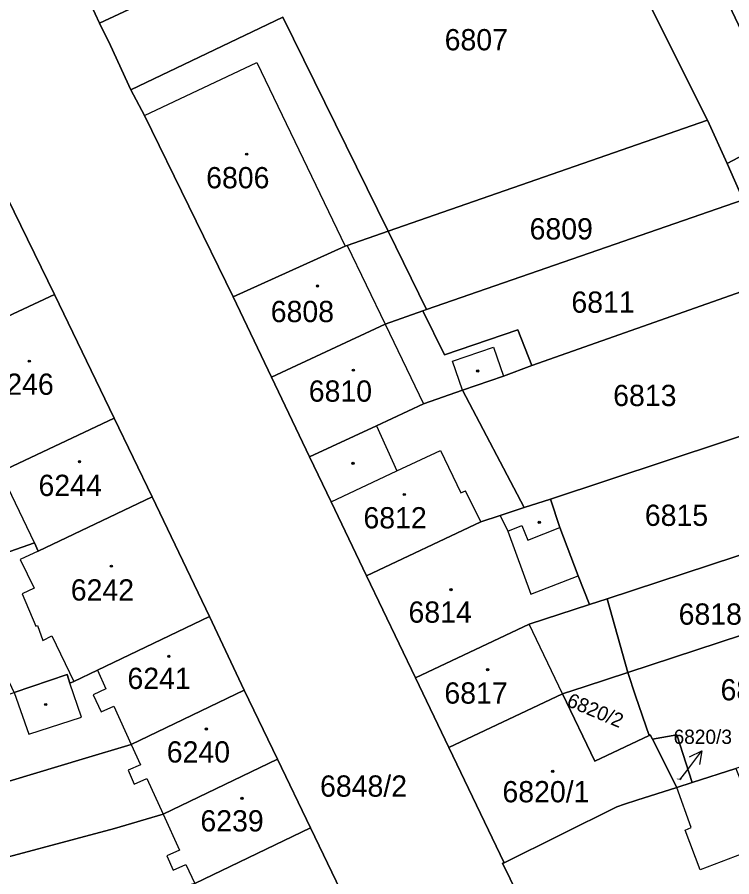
# Model space of a CAD drawing. Extents: x -596233 to -595156, y -1161235 to -1159375.
# Drawn here: x -595504.1 to -595447, y -1160101.5 to -1160032.8 of the extents above; entities that cross this region are included whole.
import ezdxf

# ---------------------------------------------------------------- set-up
doc = ezdxf.new("R2010")
doc.units = 0
for name, color, linetype in [('KN_CAR_KR', 7, 'Continuous'), ('KN_KULTURY', 7, 'Continuous'), ('KN_PARC_CIS_POM', 7, 'Continuous'), ('KN_PARC_CIS_POZ', 7, 'Continuous'), ('KN_PARC_CIS_STAV', 7, 'Continuous'), ('KN_PARC_PLOCHA', 7, 'Continuous'), ('PARC_C_SIPKA', 7, 'Continuous'), ('parcely_l', 7, 'Continuous')]:
    doc.layers.add(name, color=color, linetype=linetype)

msp = doc.modelspace()

# ---------------------------------------------------------------- linework, layer by layer
at = {"layer": 'KN_CAR_KR'}
for points in [[(-595493.94, -1160040.65), (-595484.95, -1160036.42)], [(-595484.95, -1160036.42), (-595477.89, -1160051.1)], [(-595477.75, -1160051.04), (-595474.71, -1160057.33)], [(-595474.71, -1160057.33), (-595471.63, -1160063.71)], [(-595469.32, -1160060.3), (-595466.04, -1160059.17)], [(-595466.04, -1160059.17), (-595465.25, -1160061.51)], [(-595468.52, -1160062.61), (-595469.32, -1160060.3)], [(-595475.39, -1160065.46), (-595473.77, -1160069.08)], [(-595473.77, -1160069.08), (-595470.29, -1160067.44)], [(-595470.29, -1160067.44), (-595468.66, -1160070.83)], [(-595502.74, -1160074.83), (-595505.44, -1160069.16)], [(-595479.01, -1160071.55), (-595473.77, -1160069.08)], [(-595468.66, -1160070.83), (-595468.29, -1160070.68)], [(-595467.06, -1160073.15), (-595468.29, -1160070.68)], [(-595465.51, -1160072.64), (-595464.89, -1160073.89)], [(-595464.89, -1160073.89), (-595463.77, -1160073.44)], [(-595463.77, -1160073.44), (-595463.31, -1160074.61)], [(-595463.31, -1160074.61), (-595460.74, -1160073.59)], [(-595464.89, -1160073.89), (-595463.07, -1160078.93)], [(-595502.43, -1160075.48), (-595503.87, -1160076.17)], [(-595503.87, -1160076.17), (-595502.76, -1160078.45)], [(-595463.07, -1160078.93), (-595459.28, -1160077.47)], [(-595502.76, -1160078.45), (-595503.7, -1160078.91)], [(-595503.7, -1160078.91), (-595502.61, -1160081.48)], [(-595502.61, -1160081.48), (-595502.48, -1160081.42)], [(-595502.48, -1160081.42), (-595502.06, -1160082.62)], [(-595460.52, -1160086.9), (-595463.2, -1160081.34)], [(-595502.06, -1160082.62), (-595501.34, -1160082.27)], [(-595501.34, -1160082.27), (-595499.58, -1160085.9)], [(-595497.7, -1160085), (-595497.02, -1160086.5)], [(-595498.98, -1160088.76), (-595499.89, -1160086.05)], [(-595504.35, -1160086.79), (-595503.18, -1160090.13)], [(-595497.02, -1160086.5), (-595498.03, -1160086.97)], [(-595498.03, -1160086.97), (-595497.41, -1160088.33)], [(-595497.41, -1160088.33), (-595496.39, -1160087.87)], [(-595496.39, -1160087.87), (-595494.99, -1160090.94)], [(-595503.18, -1160090.13), (-595498.98, -1160088.76)], [(-595494.99, -1160090.94), (-595494.25, -1160092.56)], [(-595494.25, -1160092.56), (-595495.25, -1160092.99)], [(-595495.25, -1160092.99), (-595494.75, -1160094.13)], [(-595494.75, -1160094.13), (-595493.75, -1160093.67)], [(-595493.75, -1160093.67), (-595492.44, -1160096.53)], [(-595444.9, -1160099.62), (-595445.04, -1160099.25), (-595449.53, -1160100.96), (-595450.73, -1160097.79), (-595450.24, -1160097.58), (-595451.4, -1160094.38)], [(-595492.44, -1160096.53), (-595491.13, -1160099.4)], [(-595491.13, -1160099.4), (-595492.15, -1160099.86)], [(-595492.15, -1160099.86), (-595491.64, -1160101)], [(-595491.64, -1160101), (-595490.62, -1160100.53)], [(-595490.62, -1160100.53), (-595489.92, -1160102.05)]]:
    msp.add_lwpolyline(points, dxfattribs=at)
at = {"layer": 'KN_KULTURY'}
for centre, radius in [((-595485.77, -1160043.75), 0.09), ((-595485.77, -1160043.75), 0.0398), ((-595480.11, -1160054.29), 0.09), ((-595480.11, -1160054.29), 0.0398), ((-595503.15, -1160060.3), 0.09), ((-595503.15, -1160060.3), 0.0398), ((-595477.24, -1160061.02), 0.09), ((-595477.24, -1160061.02), 0.0398), ((-595467.3, -1160061.09), 0.09), ((-595467.3, -1160061.09), 0.0398), ((-595499.13, -1160068.34), 0.09), ((-595499.13, -1160068.34), 0.0398), ((-595477.27, -1160068.47), 0.09), ((-595477.27, -1160068.47), 0.0398), ((-595473.17, -1160070.96), 0.09), ((-595473.17, -1160070.96), 0.0398), ((-595462.38, -1160073.19), 0.09), ((-595462.38, -1160073.19), 0.0398), ((-595496.58, -1160076.69), 0.09), ((-595496.58, -1160076.69), 0.0398), ((-595469.44, -1160078.56), 0.09), ((-595469.44, -1160078.56), 0.0398), ((-595491.99, -1160083.9), 0.09), ((-595491.99, -1160083.9), 0.0398), ((-595466.51, -1160084.96), 0.09), ((-595466.51, -1160084.96), 0.0398), ((-595501.83, -1160087.75), 0.09), ((-595501.83, -1160087.75), 0.0398), ((-595488.99, -1160089.71), 0.09), ((-595488.99, -1160089.71), 0.0398), ((-595461.31, -1160093.1), 0.09), ((-595461.31, -1160093.1), 0.0398), ((-595486.15, -1160095.25), 0.09), ((-595486.15, -1160095.25), 0.0398)]:
    msp.add_circle(centre, radius, dxfattribs=at)
at = {"layer": 'KN_PARC_PLOCHA'}
for points in [[(-595370.66, -1159982.51), (-595383.62, -1159988.37), (-595384.8, -1159988.91), (-595396.25, -1159994.64), (-595401.63, -1159997.2), (-595446.84, -1160018.63), (-595452.27, -1160021.15), (-595442.45, -1160041.88), (-595447.38, -1160044.51), (-595448.95, -1160041.02), (-595456.31, -1160026.28), (-595465.43, -1160023.47), (-595465.73, -1160022.86), (-595449.79, -1160015.51), (-595393.91, -1159989.04), (-595388.81, -1159987.77), (-595371.9, -1159979.72)], [(-595499.33, -1159989.01), (-595508.24, -1159993.19), (-595499.43, -1160011.28), (-595492.24, -1160026.06), (-595484.15, -1160022.01), (-595482.84, -1160024), (-595481.63, -1160025.84), (-595497.53, -1160033.27), (-595499.26, -1160029.53), (-595505.27, -1160017.48), (-595516.97, -1159993.45), (-595517.07, -1159992.25), (-595516.88, -1159991.13), (-595516.34, -1159990.17), (-595515.58, -1159989.46), (-595502.19, -1159983.08)], [(-595394.56, -1159998.22), (-595390.05, -1160007.78), (-595386.48, -1160015.36), (-595392, -1160017.91), (-595391.13, -1160020.12), (-595379.95, -1160014.99), (-595375.93, -1160024.33), (-595388.83, -1160029.93), (-595390.02, -1160027.09), (-595402.97, -1160033.4), (-595406.16, -1160026.42), (-595410.19, -1160028.27), (-595404.65, -1160039.32), (-595412.81, -1160043.67), (-595414.99, -1160039.05), (-595443.86, -1160052.68), (-595446.09, -1160047.4), (-595447.38, -1160044.51), (-595442.45, -1160041.88), (-595452.27, -1160021.15), (-595446.84, -1160018.63), (-595401.63, -1159997.2), (-595396.25, -1159994.64)], [(-595465.73, -1160022.86), (-595465.43, -1160023.47), (-595456.31, -1160026.28), (-595448.95, -1160041.02), (-595474.47, -1160049.9), (-595482.88, -1160032.81), (-595495.03, -1160038.6), (-595496.65, -1160035.07), (-595497.53, -1160033.27), (-595481.63, -1160025.84), (-595474.26, -1160022.44), (-595467.59, -1160019.14)], [(-595474.47, -1160049.9), (-595477.75, -1160051.04), (-595477.89, -1160051.1), (-595486.84, -1160055.17), (-595493.94, -1160040.65), (-595495.03, -1160038.6), (-595482.88, -1160032.81)], [(-595447.38, -1160044.51), (-595446.09, -1160047.4), (-595471.41, -1160056.18), (-595474.47, -1160049.9), (-595448.95, -1160041.02)], [(-595501.14, -1160054.98), (-595510.33, -1160059.26), (-595511.18, -1160059.35), (-595514.32, -1160059.76), (-595514.63, -1160059.88), (-595517.75, -1160052.96), (-595517.37, -1160052.83), (-595513.96, -1160051.67), (-595504.89, -1160047.26)], [(-595443.86, -1160052.68), (-595443.41, -1160053.75), (-595462.98, -1160060.66), (-595464.11, -1160057.8), (-595469.97, -1160059.79), (-595471.69, -1160056.28), (-595471.41, -1160056.18), (-595446.09, -1160047.4)], [(-595471.41, -1160056.18), (-595471.69, -1160056.28), (-595474.71, -1160057.33), (-595483.78, -1160061.58), (-595486.84, -1160055.17), (-595477.89, -1160051.1), (-595477.75, -1160051.04), (-595474.47, -1160049.9)], [(-595438.76, -1160063.81), (-595442.92, -1160065.18), (-595461.5, -1160071.32), (-595463.59, -1160072.01), (-595468.52, -1160062.61), (-595465.25, -1160061.51), (-595462.98, -1160060.66), (-595443.41, -1160053.75)], [(-595496.36, -1160064.85), (-595505.44, -1160069.16), (-595506.41, -1160069.26), (-595506.71, -1160069.29), (-595509.59, -1160069.9), (-595510.25, -1160070.13), (-595512.25, -1160064.9), (-595513.19, -1160062.45), (-595514.01, -1160062.54), (-595514.81, -1160059.94), (-595514.63, -1160059.88), (-595514.32, -1160059.76), (-595511.18, -1160059.35), (-595510.33, -1160059.26), (-595501.14, -1160054.98)], [(-595462.98, -1160060.66), (-595465.25, -1160061.51), (-595468.52, -1160062.61), (-595471.63, -1160063.71), (-595475.39, -1160065.46), (-595480.74, -1160067.95), (-595483.78, -1160061.58), (-595474.71, -1160057.33), (-595471.69, -1160056.28), (-595469.97, -1160059.79), (-595464.11, -1160057.8)], [(-595463.59, -1160072.01), (-595465.51, -1160072.64), (-595467.06, -1160073.15), (-595476.19, -1160077.46), (-595479.01, -1160071.55), (-595480.74, -1160067.95), (-595475.39, -1160065.46), (-595471.63, -1160063.71), (-595468.52, -1160062.61)], [(-595493.31, -1160071.14), (-595502.43, -1160075.48), (-595502.74, -1160074.83), (-595507.22, -1160076.4), (-595509.59, -1160069.9), (-595506.71, -1160069.29), (-595506.41, -1160069.26), (-595505.44, -1160069.16), (-595496.36, -1160064.85)], [(-595440.53, -1160073.9), (-595456.96, -1160079.29), (-595458.38, -1160079.76), (-595459.28, -1160077.47), (-595460.74, -1160073.59), (-595461.5, -1160071.32), (-595442.92, -1160065.18)], [(-595488.75, -1160080.72), (-595497.7, -1160085), (-595499.58, -1160085.9), (-595499.89, -1160086.05), (-595500.12, -1160085.35), (-595504.35, -1160086.79), (-595508.97, -1160077.01), (-595507.22, -1160076.4), (-595502.74, -1160074.83), (-595502.43, -1160075.48), (-595493.31, -1160071.14)], [(-595458.38, -1160079.76), (-595463.2, -1160081.34), (-595472.29, -1160085.62), (-595476.19, -1160077.46), (-595467.06, -1160073.15), (-595465.51, -1160072.64), (-595463.59, -1160072.01), (-595461.5, -1160071.32), (-595460.74, -1160073.59), (-595459.28, -1160077.47)], [(-595440.45, -1160074.17), (-595438.83, -1160079.78), (-595455.3, -1160085.19), (-595456.96, -1160079.29), (-595440.53, -1160073.9)], [(-595455.3, -1160085.19), (-595458.71, -1160086.31), (-595460.52, -1160086.9), (-595469.62, -1160091.2), (-595472.29, -1160085.62), (-595463.2, -1160081.34), (-595458.38, -1160079.76), (-595456.96, -1160079.29)], [(-595435.31, -1160089.22), (-595446.67, -1160092.86), (-595450.17, -1160093.99), (-595451.39, -1160090.18), (-595453.34, -1160090.52), (-595453.51, -1160090.18), (-595453.6, -1160090.22), (-595454.7, -1160087.05), (-595455.3, -1160085.19), (-595438.83, -1160079.78)], [(-595485.96, -1160086.6), (-595494.99, -1160090.94), (-595498.92, -1160092.12), (-595510.09, -1160095.47), (-595512.1, -1160089.31), (-595504.35, -1160086.79), (-595500.12, -1160085.35), (-595499.89, -1160086.05), (-595499.58, -1160085.9), (-595497.7, -1160085), (-595488.75, -1160080.72)], [(-595453.6, -1160090.22), (-595457.94, -1160092.28), (-595460.52, -1160086.9), (-595458.71, -1160086.31), (-595455.3, -1160085.19), (-595454.7, -1160087.05)], [(-595483.31, -1160092.12), (-595492.44, -1160096.53), (-595496.33, -1160097.66), (-595508.33, -1160100.85), (-595510.09, -1160095.47), (-595498.92, -1160092.12), (-595494.99, -1160090.94), (-595485.96, -1160086.6)], [(-595453.6, -1160090.22), (-595453.51, -1160090.18), (-595453.34, -1160090.52), (-595451.4, -1160094.38), (-595454.59, -1160095.41), (-595455.57, -1160095.72), (-595456.19, -1160095.92), (-595465.18, -1160100.4), (-595469.62, -1160091.2), (-595460.52, -1160086.9), (-595457.94, -1160092.28)], [(-595450.17, -1160093.99), (-595451.4, -1160094.38), (-595453.34, -1160090.52), (-595451.39, -1160090.18)], [(-595480.67, -1160097.61), (-595489.92, -1160102.05), (-595493.77, -1160103.14), (-595505.67, -1160106.38), (-595506.64, -1160106.65), (-595507.64, -1160102.96), (-595508.33, -1160100.85), (-595496.33, -1160097.66), (-595492.44, -1160096.53), (-595483.31, -1160092.12)], [(-595441.69, -1160108.05), (-595443.39, -1160108.54), (-595444.65, -1160108.9), (-595445.8, -1160109.23), (-595448, -1160109.87), (-595449.47, -1160110.3), (-595458.38, -1160114.15), (-595458.55, -1160114.25), (-595460.04, -1160111.19), (-595459.88, -1160111.12), (-595463.32, -1160104.18), (-595463.45, -1160104.25), (-595465.32, -1160100.43), (-595465.18, -1160100.4), (-595456.19, -1160095.92), (-595455.57, -1160095.72), (-595454.59, -1160095.41), (-595451.4, -1160094.38), (-595450.17, -1160093.99), (-595446.67, -1160092.86), (-595444.1, -1160099.37), (-595444.9, -1160099.62)], [(-595475.88, -1160107.58), (-595485.38, -1160112.01), (-595489.24, -1160113.06), (-595493.77, -1160103.14), (-595489.92, -1160102.05), (-595480.67, -1160097.61)]]:
    msp.add_lwpolyline(points, close=True, dxfattribs=at)
for points in [[(-595499.26, -1160029.53), (-595497.53, -1160033.27), (-595496.65, -1160035.07), (-595495.03, -1160038.6), (-595493.94, -1160040.65), (-595486.84, -1160055.17), (-595483.78, -1160061.58), (-595480.74, -1160067.95), (-595479.01, -1160071.55), (-595476.19, -1160077.46), (-595472.29, -1160085.62), (-595469.62, -1160091.2), (-595465.18, -1160100.4), (-595465.32, -1160100.43), (-595463.45, -1160104.25), (-595463.32, -1160104.18), (-595459.88, -1160111.12), (-595460.04, -1160111.19), (-595458.55, -1160114.25), (-595458.38, -1160114.15), (-595455.53, -1160119.96), (-595452.66, -1160125.87), (-595449.79, -1160131.72), (-595446.94, -1160137.6)], [(-595446.04, -1160169.57), (-595449.51, -1160162.6), (-595452.63, -1160155.9), (-595456.02, -1160148.88), (-595460.29, -1160140.02), (-595463.12, -1160134.12), (-595465.92, -1160128.3), (-595468.59, -1160122.75), (-595471.26, -1160117.2), (-595475.88, -1160107.58), (-595480.67, -1160097.61), (-595483.31, -1160092.12), (-595485.96, -1160086.6), (-595488.75, -1160080.72), (-595493.31, -1160071.14), (-595496.36, -1160064.85), (-595501.14, -1160054.98), (-595504.89, -1160047.26), (-595508.59, -1160039.62), (-595512.33, -1160031.9)]]:
    msp.add_lwpolyline(points, dxfattribs=at)
at = {"layer": 'PARC_C_SIPKA'}
for points in [[(-595451.14, -1160093.76), (-595450.6, -1160093.05), (-595449.3825, -1160091.4507)], [(-595450.386, -1160091.9435), (-595449.3825, -1160091.4507), (-595449.5904, -1160092.5492)]]:
    msp.add_lwpolyline(points, dxfattribs=at)
at = {"layer": 'parcely_l'}
for points in [[(-595396.25, -1159994.64), (-595401.63, -1159997.2), (-595446.84, -1160018.63), (-595452.27, -1160021.15), (-595442.45, -1160041.88), (-595447.38, -1160044.51)], [(-595505.27, -1160017.48), (-595499.26, -1160029.53), (-595497.53, -1160033.27)], [(-595448.95, -1160041.02), (-595456.31, -1160026.28), (-595465.43, -1160023.47), (-595465.73, -1160022.86)], [(-595497.53, -1160033.27), (-595481.63, -1160025.84)], [(-595495.03, -1160038.6), (-595496.65, -1160035.07), (-595497.53, -1160033.27)], [(-595495.03, -1160038.6), (-595482.88, -1160032.81), (-595474.47, -1160049.9)], [(-595486.84, -1160055.17), (-595493.94, -1160040.65), (-595495.03, -1160038.6)], [(-595448.95, -1160041.02), (-595474.47, -1160049.9)], [(-595447.38, -1160044.51), (-595448.95, -1160041.02)], [(-595447.38, -1160044.51), (-595446.09, -1160047.4)], [(-595501.14, -1160054.98), (-595504.89, -1160047.26)], [(-595446.09, -1160047.4), (-595471.41, -1160056.18)], [(-595486.84, -1160055.17), (-595477.89, -1160051.1), (-595477.75, -1160051.04), (-595474.47, -1160049.9)], [(-595474.47, -1160049.9), (-595471.41, -1160056.18)], [(-595462.98, -1160060.66), (-595443.41, -1160053.75)], [(-595514.63, -1160059.88), (-595514.32, -1160059.76), (-595511.18, -1160059.35), (-595510.33, -1160059.26), (-595501.14, -1160054.98)], [(-595496.36, -1160064.85), (-595501.14, -1160054.98)], [(-595483.78, -1160061.58), (-595486.84, -1160055.17)], [(-595483.78, -1160061.58), (-595474.71, -1160057.33), (-595471.69, -1160056.28)], [(-595471.41, -1160056.18), (-595471.69, -1160056.28)], [(-595471.69, -1160056.28), (-595469.97, -1160059.79), (-595464.11, -1160057.8), (-595462.98, -1160060.66)], [(-595462.98, -1160060.66), (-595465.25, -1160061.51), (-595468.52, -1160062.61)], [(-595480.74, -1160067.95), (-595483.78, -1160061.58)], [(-595468.52, -1160062.61), (-595471.63, -1160063.71), (-595475.39, -1160065.46), (-595480.74, -1160067.95)], [(-595463.59, -1160072.01), (-595468.52, -1160062.61)], [(-595509.59, -1160069.9), (-595506.71, -1160069.29), (-595506.41, -1160069.26), (-595505.44, -1160069.16), (-595496.36, -1160064.85)], [(-595496.36, -1160064.85), (-595493.31, -1160071.14)], [(-595442.92, -1160065.18), (-595461.5, -1160071.32)], [(-595476.19, -1160077.46), (-595479.01, -1160071.55), (-595480.74, -1160067.95)], [(-595493.31, -1160071.14), (-595502.43, -1160075.48), (-595502.74, -1160074.83), (-595507.22, -1160076.4)], [(-595488.75, -1160080.72), (-595493.31, -1160071.14)], [(-595461.5, -1160071.32), (-595463.59, -1160072.01)], [(-595458.38, -1160079.76), (-595459.28, -1160077.47), (-595460.74, -1160073.59), (-595461.5, -1160071.32)], [(-595463.59, -1160072.01), (-595465.51, -1160072.64), (-595467.06, -1160073.15), (-595476.19, -1160077.46)], [(-595440.53, -1160073.9), (-595456.96, -1160079.29)], [(-595476.19, -1160077.46), (-595472.29, -1160085.62)], [(-595458.38, -1160079.76), (-595456.96, -1160079.29)], [(-595456.96, -1160079.29), (-595455.3, -1160085.19)], [(-595472.29, -1160085.62), (-595463.2, -1160081.34), (-595458.38, -1160079.76)], [(-595455.3, -1160085.19), (-595438.83, -1160079.78)], [(-595488.75, -1160080.72), (-595497.7, -1160085), (-595499.58, -1160085.9), (-595499.89, -1160086.05), (-595500.12, -1160085.35), (-595504.35, -1160086.79)], [(-595485.96, -1160086.6), (-595488.75, -1160080.72)], [(-595460.52, -1160086.9), (-595458.71, -1160086.31), (-595455.3, -1160085.19)], [(-595455.3, -1160085.19), (-595454.7, -1160087.05), (-595453.6, -1160090.22)], [(-595469.62, -1160091.2), (-595472.29, -1160085.62)], [(-595510.09, -1160095.47), (-595498.92, -1160092.12), (-595494.99, -1160090.94), (-595485.96, -1160086.6)], [(-595483.31, -1160092.12), (-595485.96, -1160086.6)], [(-595460.52, -1160086.9), (-595469.62, -1160091.2)], [(-595453.6, -1160090.22), (-595457.94, -1160092.28), (-595460.52, -1160086.9)], [(-595453.34, -1160090.52), (-595453.51, -1160090.18), (-595453.6, -1160090.22)], [(-595450.17, -1160093.99), (-595451.39, -1160090.18), (-595453.34, -1160090.52)], [(-595451.4, -1160094.38), (-595453.34, -1160090.52)], [(-595469.62, -1160091.2), (-595465.18, -1160100.4)], [(-595483.31, -1160092.12), (-595492.44, -1160096.53), (-595496.33, -1160097.66), (-595508.33, -1160100.85)], [(-595480.67, -1160097.61), (-595483.31, -1160092.12)], [(-595446.67, -1160092.86), (-595450.17, -1160093.99)], [(-595465.18, -1160100.4), (-595456.19, -1160095.92), (-595455.57, -1160095.72), (-595454.59, -1160095.41), (-595451.4, -1160094.38)], [(-595450.17, -1160093.99), (-595451.4, -1160094.38)], [(-595493.77, -1160103.14), (-595489.92, -1160102.05), (-595480.67, -1160097.61)], [(-595480.67, -1160097.61), (-595475.88, -1160107.58)], [(-595465.18, -1160100.4), (-595465.32, -1160100.43), (-595463.45, -1160104.25), (-595463.32, -1160104.18), (-595459.88, -1160111.12), (-595460.04, -1160111.19), (-595458.55, -1160114.25), (-595458.38, -1160114.15)]]:
    msp.add_lwpolyline(points, dxfattribs=at)

# ---------------------------------------------------------------- texts
at = {"layer": 'KN_PARC_CIS_POM'}
msp.add_text('6820/3', height=0.1, dxfattribs=at).set_placement((-595451.4233, -1160093.76))
at = {"layer": 'KN_PARC_CIS_POZ'}
for s, height, p in [('6807', 1.7, (-595469.9466, -1160035.45)), ('6809', 1.7, (-595463.1566, -1160050.57)), ('6811', 1.7, (-595459.8166, -1160056.43)), ('6813', 1.7, (-595456.4766, -1160063.89)), ('6815', 1.7, (-595453.9466, -1160073.47)), ('6818', 1.7, (-595451.2466, -1160081.37)), ('6821', 1.7, (-595447.8966, -1160087.42)), ('6820/3', 1.14, (-595451.65, -1160090.9)), ('6848/2', 1.7, (-595479.9066, -1160095.12))]:
    msp.add_text(s, height=height, dxfattribs=at).set_placement(p)
msp.add_text('6820/2', height=1.14, rotation=337.260287, dxfattribs=at).set_placement((-595460.2689, -1160087.8415))
at = {"layer": 'KN_PARC_CIS_STAV'}
for s, p in [('6806', (-595489.0066, -1160046.48)), ('6808', (-595483.8466, -1160057.18)), ('6246', (-595506.2466, -1160062.99)), ('6810', (-595480.8066, -1160063.54)), ('6244', (-595502.4066, -1160071.08)), ('6812', (-595476.4366, -1160073.67)), ('6242', (-595499.8266, -1160079.44)), ('6814', (-595472.8366, -1160081.21)), ('6241', (-595495.2966, -1160086.51)), ('6817', (-595469.9666, -1160087.68)), ('6240', (-595492.1566, -1160092.39)), ('6820/1', (-595465.3266, -1160095.57)), ('6239', (-595489.4666, -1160097.9))]:
    msp.add_text(s, height=1.7, dxfattribs=at).set_placement(p)

doc.saveas('drawing.dxf')
